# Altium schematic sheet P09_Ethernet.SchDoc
size 513 x 386 mm
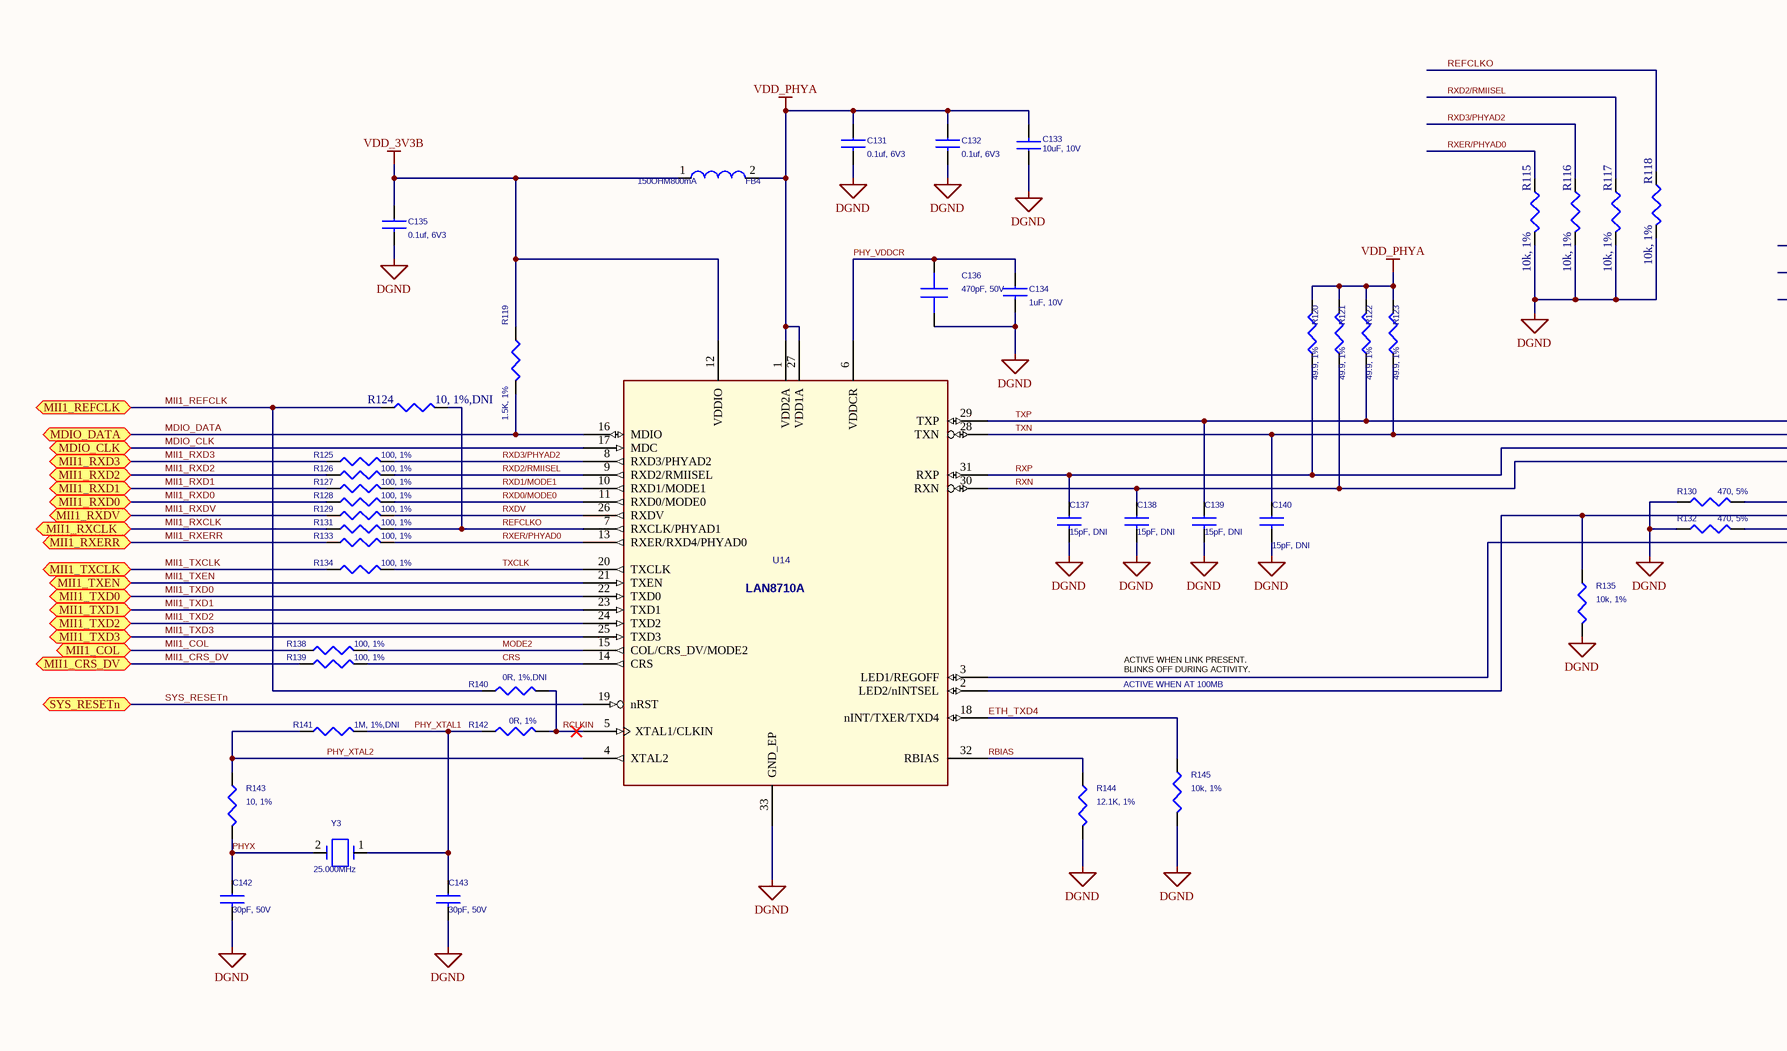
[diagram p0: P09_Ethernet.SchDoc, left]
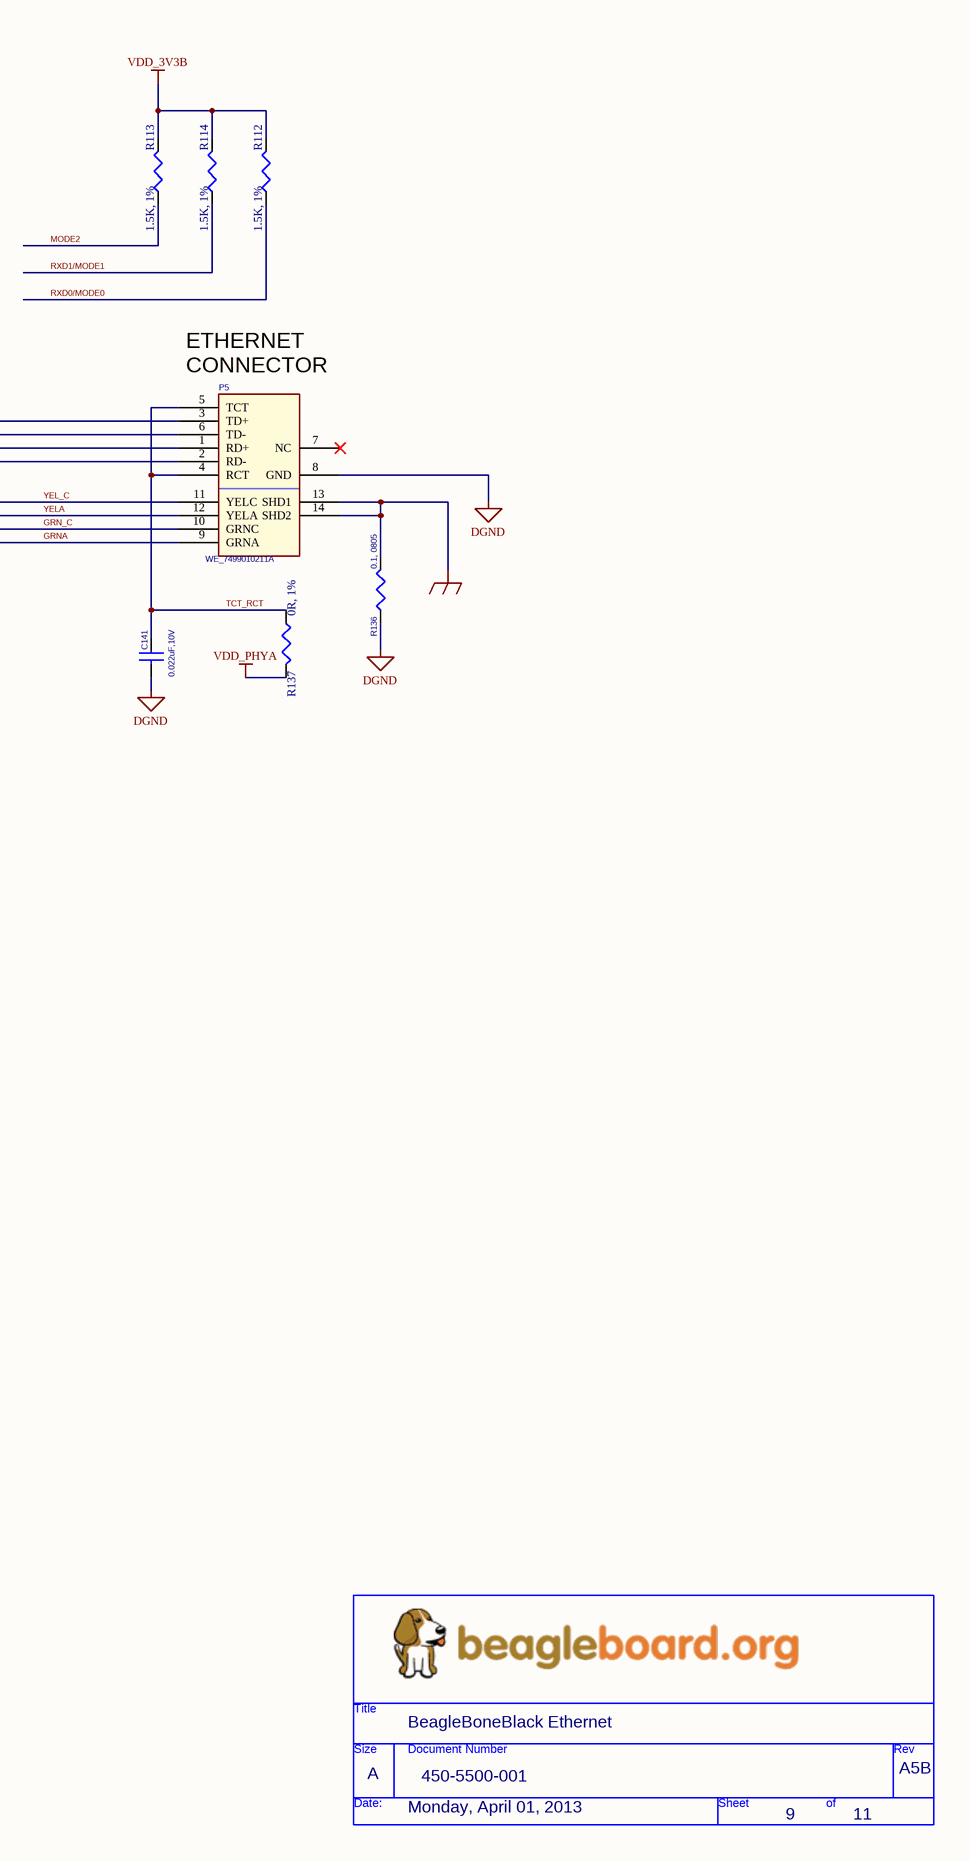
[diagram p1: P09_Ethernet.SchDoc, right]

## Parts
*  Page Create Date: Monday, April 01, 2013  Doc: 450-5500-001  RevCode: A5B  Title: BeagleBoneBlack Ethernet  Page Size: A  Page Number: 9  Page Count: 11  (hidden comment: BeagleBoard_org)  (graphical)
C131  0.1uf, 6V3  [402]
C132  0.1uf, 6V3  [402]
C133  10uF, 10V  [805]
C134  1uF, 10V  [402]
C135  0.1uf, 6V3  [402]
C136  470pF, 50V  [402]
C137  15pF, DNI  [402]
C138  15pF, DNI  [402]
C139  15pF, DNI  [402]
C140  15pF, DNI  [402]
C141  0.022uF,10V  [402]
C142  30pF, 50V  [402]
C143  30pF, 50V  [402]
FB4  150OHM800mA  [SM-7351-IND-0805]
P5  WE_7499010211A  [RJ45-7499010211A]
R112  1.5K, 1%  [402]
R113  1.5K, 1%  [402]
R114  1.5K, 1%  [402]
R115  10k, 1%  [402]
R116  10k, 1%  [402]
R117  10k, 1%  [402]
R118  10k, 1%  [402]
R119  1.5K, 1%  [402]
R120  49.9, 1%  [402]
R121  49.9, 1%  [402]
R122  49.9, 1%  [402]
R123  49.9, 1%  [402]
R124  10, 1%,DNI  [402]
R125  100, 1%  [402]
R126  100, 1%  [402]
R127  100, 1%  [402]
R128  100, 1%  [402]
R129  100, 1%  [402]
R130  470, 5%  [402]
R131  100, 1%  [402]
R132  470, 5%  [402]
R133  100, 1%  [402]
R134  100, 1%  [402]
R135  10k, 1%  [402]
R136  0.1, 0805  [805]
R137  0R, 1%  [402]
R138  100, 1%  [402]
R139  100, 1%  [402]
R140  0R, 1%,DNI  [402]
R141  1M, 1%,DNI  [402]
R142  0R, 1%  [402]
R143  10, 1%  [402]
R144  12.1K, 1%  [402]
R145  10k, 1%  [402]
U14  LAN8710A  [QFN32_5X5MM_EP3P3MM]
Y3  25.000MHz  [XTAL150SMD_125X196]

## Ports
MDIO_CLK, MDIO_DATA, MII1_COL, MII1_CRS_DV, MII1_REFCLK, MII1_RXCLK, MII1_RXD0, MII1_RXD1, MII1_RXD2, MII1_RXD3, MII1_RXDV, MII1_RXERR, MII1_TXCLK, MII1_TXD0, MII1_TXD1, MII1_TXD2, MII1_TXD3, MII1_TXEN, SYS_RESETn

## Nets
DGND: C131.2 C132.2 C133.1 C134.2 C135.2 C136.2 C137.2 C138.2 C139.2 C140.2 C141.2 C142.2 C143.2 P5.8(GND) R115.2 R116.2 R117.2 R118.2 R130.1 R132.1 R135.2 R136.1 R144.2 R145.2 U14.33(GND_EP)
GND_EARTH: P5.13(SHD1) P5.14(SHD2) R136.2
VDD_3V3B: C135.1 FB4.1 R112.2 R113.2 R114.2 R119.1 U14.12(VDDIO)
VDD_PHYA: C131.1 C132.1 C133.2 FB4.2 R120.2 R121.2 R122.2 R123.2 R137.2 U14.1(VDD2A) U14.27(VDD1A)
CRS: R139.2 U14.14(CRS)
ETH_TXD4: R145.1 U14.18(nINT/TXER/TXD4)
GRN_C: P5.10(GRNC) R132.2
GRNA: P5.9(GRNA) U14.3(LED1/REGOFF)
MDIO_CLK: U14.17(MDC) ; port MDIO_CLK
MDIO_DATA: R119.2 U14.16(MDIO) ; port MDIO_DATA
MII1_COL: R138.1 ; port MII1_COL
MII1_CRS_DV: R139.1 ; port MII1_CRS_DV
MII1_REFCLK: R124.1 R140.1 ; port MII1_REFCLK
MII1_RXCLK: R131.1 ; port MII1_RXCLK
MII1_RXD0: R128.1 ; port MII1_RXD0
MII1_RXD1: R127.1 ; port MII1_RXD1
MII1_RXD2: R126.1 ; port MII1_RXD2
MII1_RXD3: R125.1 ; port MII1_RXD3
MII1_RXDV: R129.1 ; port MII1_RXDV
MII1_RXERR: R133.1 ; port MII1_RXERR
MII1_TXCLK: R134.1 ; port MII1_TXCLK
MII1_TXD0: U14.22(TXD0) ; port MII1_TXD0
MII1_TXD1: U14.23(TXD1) ; port MII1_TXD1
MII1_TXD2: U14.24(TXD2) ; port MII1_TXD2
MII1_TXD3: U14.25(TXD3) ; port MII1_TXD3
MII1_TXEN: U14.21(TXEN) ; port MII1_TXEN
MODE2: R113.1 R138.2 U14.15(COL/CRS_DV/MODE2)
PHY_VDDCR: C134.1 C136.1 U14.6(VDDCR)
PHY_XTAL1: C143.1 R141.2 R142.1 Y3.1
PHY_XTAL2: R141.1 R143.1 U14.4(XTAL2)
PHYX: C142.1 R143.2 Y3.2
RBIAS: R144.1 U14.32(RBIAS)
RCLKIN: R140.2 R142.2 U14.5(XTAL1/CLKIN)
REFCLKO: R118.1 R124.2 R131.2 U14.7(RXCLK/PHYAD1)
RXD0/MODE0: R112.1 R128.2 U14.11(RXD0/MODE0)
RXD1/MODE1: R114.1 R127.2 U14.10(RXD1/MODE1)
RXD2/RMIISEL: R117.1 R126.2 U14.9(RXD2/RMIISEL)
RXD3/PHYAD2: R116.1 R125.2 U14.8(RXD3/PHYAD2)
RXDV: R129.2 U14.26(RXDV)
RXER/PHYAD0: R115.1 R133.2 U14.13(RXER/RXD4/PHYAD0)
RXN: C138.1 P5.2(RD-) R121.1 U14.30(RXN)
RXP: C137.1 P5.1(RD+) R120.1 U14.31(RXP)
SYS_RESETn: U14.19(nRST) ; port SYS_RESETn
TCT_RCT: C141.1 P5.4(RCT) P5.5(TCT) R137.1
TXCLK: R134.2 U14.20(TXCLK)
TXN: C140.1 P5.6(TD-) R123.1 U14.28(TXN)
TXP: C139.1 P5.3(TD+) R122.1 U14.29(TXP)
YEL_C: P5.11(YELC) R130.2
YELA: P5.12(YELA) R135.1 U14.2(LED2/nINTSEL)

Not connected (* = marked no-connect by the designer): P5 7(NC)*

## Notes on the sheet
- (near P5) ETHERNET
  CONNECTOR
- ACTIVE WHEN LINK PRESENT.
  BLINKS OFF DURING ACTIVITY.
- ACTIVE WHEN AT 100MB

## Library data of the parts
C131 C132 C135 = CAP_0.1uF_X7R_16V_10% 0402: CAP CER 0.1UF 6.3V 10% X5R 0402; Manufacturer: TDK Corporation; Manufacturer Part Number: C1005X5R0J104K050BA; Capacitance: 0.1µF
C133 = CAP_4.7uF_X5R_6.3V_10%_0603: CAP CER 10UF 10V Y5V 0805; Manufacturer: TDK Corporation; Manufacturer Part Number: C2012Y5V1A106Z; Capacitance: 10µF; Tolerance: -20%, +80%; Temperature Coefficient: Y5V (F)
C134 = CAP_1.0UF_X5R_10V_10%_0402: CAP CER 1UF 10V 10% X5R 0402; Manufacturer: AVX Corporation; Manufacturer Part Number: 0402ZD105KAT2A; Capacitance: 1.0µF
C136 = 470pF/5%/50V/C0G/0603_0: CAP CER 470PF 50V 10% X7R 0402; Manufacturer: Murata Electronics North America; Manufacturer Part Number: GRM155R71H471KA01D
C137-C140 = CAP_0402_100pF_COG_50V: CAP CER 15PF 50V 5% NP0 0402; Manufacturer: TDK Corporation; Manufacturer Part Number: C1005C0G1H150J050BA; Temperature Coefficient: C0G, NP0
C141 = CAP_0402_0.1uf_X5R_10V: CAP CER 0.022UF 10V 10% X7R 0402; Manufacturer: Taiyo Yuden; Manufacturer Part Number: LMK105B7223KV-F; Capacitance: 0.022µF
C142 C143 = CAP_30PF_COG_50V_5%_0402: CAP CER 30PF 50V 5% NP0 0402; Manufacturer: TDK Corporation; Manufacturer Part Number: C1005C0G1H300J; Temperature Coefficient: C0G, NP0
FB4 = FER_180_200_0: FERRITE 800MA 150 OHM 0805 SMD; PartName: FerriteBead150ohm800mA; Mfr: Steward; MfrNum: LI0805H151R-10; TIIntPartnumber: 1L0010; Manufacturer: Laird-Signal Integrity Products; Vendor: Digikey; DC Resistance (DCR): 150 mOhm Max; Filter Type: Differential Mode - Single; Impedance @ Frequency: 150 Ohm @ 100MHz
P5 = CONN_RJ45_MAG_WE_0: WE-RJ45 LAN Transformer
R112-R114 = RES_10K_1/16W_1%_0402: RES 1.50K OHM 1/16W 1% 0402 SMD; Manufacturer: Yageo; Manufacturer Part Number: RC0402FR-071K5L; Power (Watts): 0.063W, 1/16W; Temperature Coefficient: ±100ppm/°C
R115-R118 R135 R145 = RES_10K_1/16W_1%_0402: RES 10K OHM 1/16W 5% 0402 SMD; Manufacturer: Rohm Semiconductor; Manufacturer Part Number: MCR01MZPJ103; Power (Watts): 0.063W, 1/16W; Temperature Coefficient: ±200ppm/°C
R119 = RES_1.5K_1/16W_5%_0402: RES 1.50K OHM 1/16W 1% 0402 SMD; Manufacturer: Yageo; Manufacturer Part Number: RC0402FR-071K5L; Power (Watts): 0.063W, 1/16W; Temperature Coefficient: ±100ppm/°C
R120-R123 = RES_4.7K_0402: RES 49.9 OHM 1/16W 1% 0402 SMD; Manufacturer: Yageo; Manufacturer Part Number: RC0402FR-0749R9L; Power (Watts): 0.063W, 1/16W; Resistance (Ohms): 49.9; Temperature Coefficient: ±100ppm/°C
R124 = RES_10K_1/16W_1%_0402: Resistor 10Kohm 1/16W 1% 0402; Manufacturer: Stackpole Electronics Inc; Manufacturer Part Number: RMCF0402FT10R0; Power (Watts): 0.063W, 1/16W; Resistance (Ohms): 10; Temperature Coefficient: ±100ppm/°C
R125 R126 R129 R134 R138 = 100-1/10W-1%-0603_4: RES 100 OHM 1/10W 5% 0402 SMD; PART#: Rohm MCR03EZPFX1000; Manufacturer: Panasonic Electronic Components; Manufacturer Part Number: ERJ-2RKF1000X; Resistance (Ohms): 100; Power (Watts): 0.1W, 1/10W; Temperature Coefficient: ±100ppm/°C
R127 R128 R131 R133 R139 = RES_100_1/10W_5%_0402: RES 100 OHM 1/10W 5% 0402 SMD; Manufacturer: Panasonic Electronic Components; Manufacturer Part Number: ERJ-2RKF1000X; Resistance (Ohms): 100; Power (Watts): 0.1W, 1/10W; Temperature Coefficient: ±100ppm/°C
R130 R132 = RES_470_1/10W_5%_0402: RES 470 OHM 1/10W 5% 0402 SMD; Manufacturer: Panasonic Electronic Components; Manufacturer Part Number: ERJ-2GEJ471X; Resistance (Ohms): 470; Power (Watts): 0.1W, 1/10W; Temperature Coefficient: ±200ppm/°C
R136 = RES_0.1_0805: RES .10 OHM 1/8W 5% 0805; Manufacturer: CTS Resistor Products; Manufacturer Part Number: 73L3R10J; Resistance (Ohms): 0.1; Power (Watts): 0.125W, 1/8W; Temperature Coefficient: ±200ppm/°C
R137 R140 R142 = RES_0_1/16W_1%_0402: RES 0.0 OHM 1/16W 0402 SMD; Manufacturer: Yageo; Manufacturer Part Number: RC0402JR-070RL; Power (Watts): 0.063W, 1/16W; Resistance (Ohms): 0.0; Tolerance: Jumper
R141 = RES_1M_1/16W_1%_0402: RES 1M OHM 1/16W 1% 0402 SMD; Manufacturer: Stackpole Electronics Inc; Manufacturer Part Number: RMCF0402FT1M00; Power (Watts): 0.063W, 1/16W; Temperature Coefficient: ±100ppm/°C
R143 = RES_10K_1/16W_1%_0402: RES 10 OHM 1/16W 1% 0402 SMD; Manufacturer: Stackpole Electronics Inc; Manufacturer Part Number: RMCF0402FT10R0; Resistance (Ohms): 10; Power (Watts): 0.063W, 1/16W; Temperature Coefficient: ±100ppm/°C
R144 = RES_12.1K_1/16W_1%_0402: RES 12.1K OHM 1/16W 1% 0402 SMD; Manufacturer: Yageo; Manufacturer Part Number: RC0402FR-0712K1L; Power (Watts): 0.063W, 1/16W; Temperature Coefficient: ±100ppm/°C
U14 = LAN8710 QFN32_1: Ethernet ICs 10/100 Ethernet XCVR w/HPAutoMDIX FlexPwr; PART#: SMSC LAN8710A-EZK; Manufacturer: Microchip Technology; Manufacturer Part Number: LAN8710A-EZK-TR; Data Rate: 125 Mb/s; Number of Transceivers: 1; Standard Supported: 802.3, 802.3u; Supply Voltage - Max: 3.6 V; Supply Voltage - Min: 1.6 V, 3 V
Y3 = Suntsu ITEMP 25MHz _0.005% 20pf: Manufacturer: Abracon Corporation; Manufacturer Part Number: ABM3-25.000MHZ-B2-T; Frequency: 25MHz; Frequency Stability: ±50ppm; Frequency Tolerance: ±20ppm; Load Capacitance: 18pF; ESR (Equivalent Series Resistance): 50 Ohm; Operating Mode: Fundamental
